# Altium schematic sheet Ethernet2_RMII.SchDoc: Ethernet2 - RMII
size A3; Project: Project name; Date: Not used; ApprovedBy: Not used; CheckedBy: Not used; Author: Not used; CompanyName: STMicroelectronics; DrawnBy: Not used; Engineer: Not used; Organization: Not used; Address1: Not used; Address2: Not used; Address3: Not used; Address4: Not used; DocumentNumber: 8; Revision: Not used; SheetNumber: 8; SheetTotal: 17
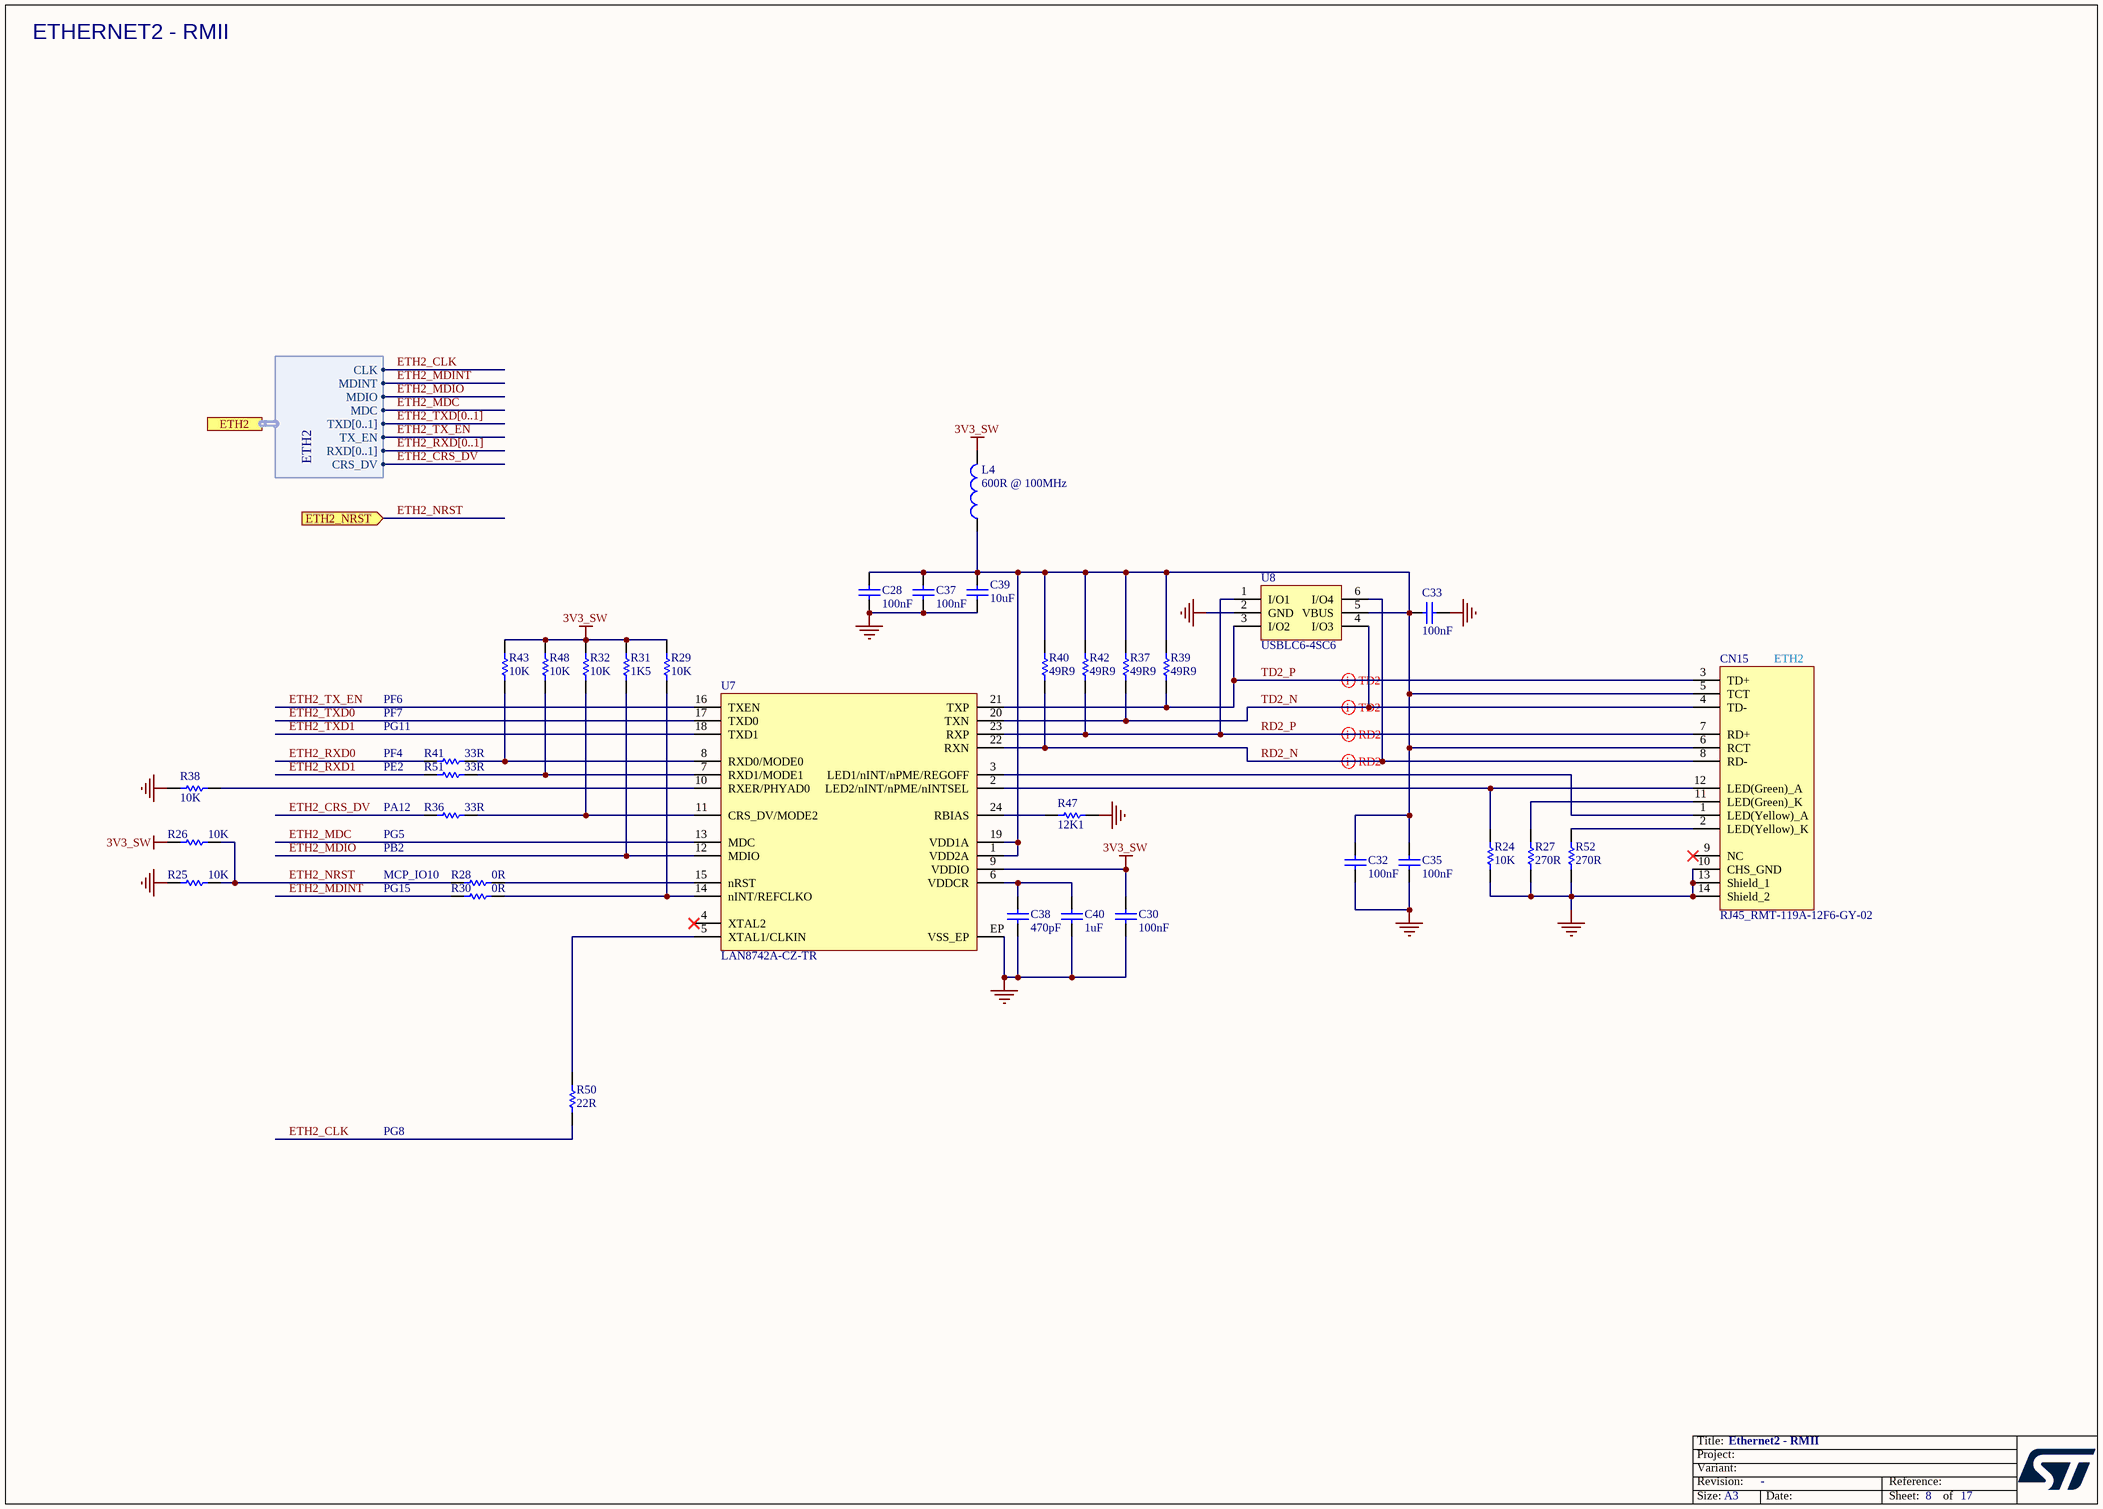
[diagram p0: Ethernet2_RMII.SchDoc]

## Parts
C28  value 100nF  [C0402]  (hidden comment: Capacitor)
C30  value 100nF  [C0402]  (hidden comment: Capacitor)
C32  value 100nF  [C0402]  (hidden comment: Capacitor)
C33  value 100nF  [C0402]  (hidden comment: Capacitor)
C35  value 100nF  [C0402]  (hidden comment: Capacitor)
C37  value 100nF  [C0402]  (hidden comment: Capacitor)
C38  value 470pF  [C0402]  (hidden comment: Capacitor)
C39  value 10uF  [C0603]  (hidden comment: Capacitor)
C40  value 1uF  [C0201_MURATA_GRM033_H0P3]  (hidden comment: Capacitor)
CN15  value RJ45_RMT-119A-12F6-GY-02  [CON_RJ45_PHC_RMT-119A-12F6-GY-02]  (hidden comment: RJ45_RTS-119A-12F6-GY-02)
L4  value 600R @ 100MHz  [L0603]  (hidden comment: BEAD)
R24  value 10K  [R0402]  (hidden comment: Resistor)
R25  value 10K  [R0402]  (hidden comment: Resistor)
R26  value 10K  [R0402]  (hidden comment: Resistor)
R27  value 270R  [R0402]  (hidden comment: Resistor)
R28  value 0R  [R0402]  (hidden comment: Resistor)
R29  value 10K  [R0402]  (hidden comment: Resistor)
R30  value 0R  [R0402]  (hidden comment: Resistor)
R31  value 1K5  [R0402]  (hidden comment: Resistor)
R32  value 10K  [R0402]  (hidden comment: Resistor)
R36  value 33R  [R0402]  (hidden comment: Resistor)
R37  value 49R9  [R0402]  (hidden comment: Resistor)
R38  value 10K  [R0402]  (hidden comment: Resistor)
R39  value 49R9  [R0402]  (hidden comment: Resistor)
R40  value 49R9  [R0402]  (hidden comment: Resistor)
R41  value 33R  [R0402]  (hidden comment: Resistor)
R42  value 49R9  [R0402]  (hidden comment: Resistor)
R43  value 10K  [R0402]  (hidden comment: Resistor)
R47  value 12K1  [R0402]  (hidden comment: Resistor)
R48  value 10K  [R0402]  (hidden comment: Resistor)
R50  value 22R  [R0402]  (hidden comment: Resistor)
R51  value 33R  [R0402]  (hidden comment: Resistor)
R52  value 270R  [R0402]  (hidden comment: Resistor)
U7  LAN8742A-CZ-TR  [ICC_VQFN24-EPAD_4X4_P050]
U8  USBLC6-4SC6  [ESD_SOT23-6L]

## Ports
ETH2 (harness ETH2), ETH2_NRST (in)

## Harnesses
ETH2: MDINT, TXD[0..1], MDIO, MDC, TX_EN, RXD[0..1], CRS_DV, CLK

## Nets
3V3_SW: C30.2 L4.2 R26.2 R29.2 R31.2 R32.2 R43.2 R48.2 U7.9(VDDIO)
GND: C28.1 C30.1 C32.1 C33.2 C35.1 C37.1 C38.1 C39.2 C40.1 CN15.10(CHS_GND) CN15.13(Shield_1) CN15.14(Shield_2) R24.1 R25.2 R27.1 R38.2 R47.2 R52.1 U7.EP(VSS_EP) U8.2(GND)
ETH2_CLK: R50.1 ; port ETH2.CLK
ETH2_CRS_DV: R36.1 ; port ETH2.CRS_DV
ETH2_MDC: U7.13(MDC) ; port ETH2.MDC
ETH2_MDINT: R30.1 ; port ETH2.MDINT
ETH2_MDIO: R31.1 U7.12(MDIO) ; port ETH2.MDIO
ETH2_NRST: R25.1 R26.1 R28.1 ; port ETH2_NRST
ETH2_RXD0: R41.1
ETH2_RXD1: R51.1
ETH2_TX_EN: U7.16(TXEN) ; port ETH2.TX_EN
ETH2_TXD0: U7.17(TXD0)
ETH2_TXD1: U7.18(TXD1)
RD2_N: CN15.8(RD-) R40.1 U7.22(RXN) U8.6(I/O4)
RD2_P: CN15.7(RD+) R42.1 U7.23(RXP) U8.1(I/O1)
TD2_N: CN15.4(TD-) R37.1 U7.20(TXN) U8.4(I/O3)
TD2_P: CN15.3(TD+) R39.1 U7.21(TXP) U8.3(I/O2)
NetC28_2: C28.2 C32.2 C33.1 C35.2 C37.2 C39.1 CN15.5(TCT) CN15.6(RCT) L4.1 R37.2 R39.2 R40.2 R42.2 U7.1(VDD2A) U7.19(VDD1A) U8.5(VBUS)
NetC38_2: C38.2 C40.2 U7.6(VDDCR)
NetCN15_1: CN15.1(LED(Yellow)_A) U7.3(LED1/nINT/nPME/REGOFF)
NetCN15_2: CN15.2(LED(Yellow)_K) R52.2
NetCN15_11: CN15.11(LED(Green)_K) R27.2
NetCN15_12: CN15.12(LED(Green)_A) R24.2 U7.2(LED2/nINT/nPME/nINTSEL)
NetR28_2: R28.2 U7.15(nRST)
NetR29_1: R29.1 R30.2 U7.14(nINT/REFCLKO)
NetR32_1: R32.1 R36.2 U7.11(CRS_DV/MODE2)
NetR38_1: R38.1 U7.10(RXER/PHYAD0)
NetR41_2: R41.2 R43.1 U7.8(RXD0/MODE0)
NetR47_1: R47.1 U7.24(RBIAS)
NetR48_1: R48.1 R51.2 U7.7(RXD1/MODE1)
NetR50_2: R50.2 U7.5(XTAL1/CLKIN)

Not connected (* = marked no-connect by the designer): CN15 9(NC)*; U7 4(XTAL2)*

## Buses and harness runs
bus ETH2_RXD[0..1]
bus ETH2_TXD[0..1]

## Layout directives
differential pair: RD2_N, RD2_P, TD2_N, TD2_P

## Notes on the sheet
- ETHERNET2 - RMII
- PF6
- PF7
- ETH2
- PF4
- PE2
- PG11
- PA12
- (near R36) PG5
- PB2
- PG15
- MCP_IO10
- PG8

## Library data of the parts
C28 C30 C32 C33 C35 C37 = MCD-00006: Capacitor, MLCC, 100nF, 16V, X7R, +/-10%, 0402, T=0.5mm; Manufacturer_Part_Number: CC0402KRX7R7BB104; Manufacturer: YAGEO; Part_Preference: Recommended; Partial_Alternate_Internal_Part_Number: MCD-03299; Order_Code_RS: 9402047; Component_Country_Of_Origin: China; ShowFields: YES; ID: 2474
C38 = MCD-00724: Capacitor, MLCC, 470pF, 50V, NPO, +/-5%, 0402, T=0.5mm; Manufacturer_Part_Number: CC0402JRNPO9BN471; Manufacturer: YAGEO; Part_Preference: Recommended; Order_Code_RS: 199-2186; Component_Country_Of_Origin: China; ShowFields: YES; ID: 3023
C39 = MCD-00099: Capacitor, MLCC, 10uF, 10V, X5R, +/-10%, 0603, T=0.8mm; Manufacturer_Part_Number: GRM188R61A106KE69; Manufacturer: MURATA; Part_Preference: Recommended; Partial_Alternate_Internal_Part_Number: MCD-03152; Order_Code_RS: 2494233; Component_Country_Of_Origin: Japan°°; ShowFields: YES; ID: 2770
C40 = MCD-02377: Capacitor, MLCC, 1uF, 6.3V, X5R, +/-20%, 0201, T=0,3mm; Manufacturer_Part_Number: GRM033R60J105MEA2; Manufacturer: MURATA; Part_Preference: Recommended; Partial_Alternate_Internal_Part_Number: MCD-04356; Order_Code_RS: 820-0643; Component_Country_Of_Origin: Japan°; ShowFields: YES; ID: 4483
CN15 = MCD-02475: connector_RJ45, 10/100 Ethernet integrated MAG with integrate Green and Yellow LED, T= 13.61mm; Part_Preference: Recommended; Manufacturer: PENGHUI; Manufacturer_Part_Number: RMT-119A-12F6-GY-02; ShowFields: YES; ID: 4581; Component_Country_Of_Origin: China
L4 = MCD-00047: Ferrite bead, 600R @1 00MHz, +/-25%, 350mA, 0R5, 0603, T=0.8mm; Part_Type: Inductor; Manufacturer_Part_Number: FCM1608KF-601T03; Manufacturer: TAI-TECH; Part_Preference: Recommended; Partial_Alternate_Internal_Part_Number: MCD-02959; Component_Country_Of_Origin: Unknown; ShowFields: YES; ID: 2546
R24 R29 R32 R38 R43 R48 = MCD-00053: Resistor, 10K, 0402, +/-1%, 1/16W; Manufacturer_Part_Number: RC0402FR-0710KL; Manufacturer: YAGEO; BMS_Part_Number: 9131590; Part_Preference: Recommended; Order_Code_RS: 9239359; Component_Country_Of_Origin: China; ShowFields: YES; ID: 2539
R25 R26 = MCD-00053: Resistor, 10K, 0402, +/-1%, 1/16W; Manufacturer_Part_Number: RC0402FR-0710KL; Manufacturer: YAGEO; Part_Preference: Recommended; BMS_Part_Number: 9131590; Order_Code_RS: 9239359; Component_Country_Of_Origin: China; ShowFields: YES; ID: 2539
R27 R52 = MCD-00441: Resistor, 270R, 0402, +/-1%, 1/16W; Manufacturer_Part_Number: RC0402FR-07270RL; Manufacturer: YAGEO; Part_Preference: Recommended; Component_Country_Of_Origin: China; ShowFields: YES; ID: 2838
R28 = MCD-00052: Resistor, 0R, 0402, +/-5%, 1/16W; Part_Preference: Recommended; Manufacturer: YAGEO; Manufacturer_Part_Number: RC0402JR-070RL; Order_Code_RS: 9232516RL; Component_Country_Of_Origin: China; ShowFields: YES; ID: 2540
R30 = MCD-00052: Resistor, 0R, 0402, +/-5%, 1/16W; Manufacturer_Part_Number: RC0402JR-070RL; Manufacturer: YAGEO; Part_Preference: Recommended; Order_Code_RS: 9232516RL; Component_Country_Of_Origin: China; ShowFields: YES; ID: 2540
R31 = MCD-00068: Resistor, 1K5, 0402, +/-1%, 1/16W; Manufacturer_Part_Number: RC0402FR-071K5L; Manufacturer: YAGEO; Part_Preference: Recommended; Order_Code_RS: 9239251; Component_Country_Of_Origin: China; ShowFields: YES; ID: 2524
R36 R41 R51 = MCD-00455: Resistor, 33R, 0402, +/-1%, 1/16W; Manufacturer_Part_Number: RC0402FR-0733RL; Manufacturer: YAGEO; Part_Preference: Recommended; Component_Country_Of_Origin: China; ShowFields: YES; ID: 2821
R37 R39 R40 R42 = MCD-00565: Resistor, 49R9, 0402, +/-1%, 1/16W; Manufacturer_Part_Number: RC0402FR-0749R9L; Manufacturer: YAGEO; Part_Preference: Recommended; Component_Country_Of_Origin: China; ShowFields: YES; ID: 3178
R47 = MCD-00723: Resistor, 12K1, 0402, +/-1%, 1/16W; Manufacturer_Part_Number: RC0402FR-0712K1L; Manufacturer: YAGEO; Part_Preference: Recommended; Component_Country_Of_Origin: China; ShowFields: YES; ID: 3022
R50 = MCD-00189: Resistor, 22R, 0402, +/-1%, 1/16W; Manufacturer_Part_Number: RC0402FR-0722RL; Manufacturer: YAGEO; Part_Preference: Recommended; Component_Country_Of_Origin: China; ShowFields: YES; ID: 2677
U7 = MCD-00719: 10/100M RMII Ethernet transceiver; Part_Type: IC; Manufacturer: MICROCHIP; BMS_Part_Number: 9177984; Part_Preference: Recommended; Partial_Alternate_Internal_Part_Number: MCD-03200; Component_Country_Of_Origin: Unknown; ShowFields: YES; ID: 3026; Order_Code_RS: 215-3925
U8 = MCD-00250: Very low capacitance ESD protection , 4 lines; Part_Type: Diode; Manufacturer: STMICROELECTRONICS; BMS_Part_Number: 9151001; Part_Preference: Recommended; Manufacturer_HQ_COO: EU; Component_Country_Of_Origin: China; ShowFields: YES; ID: 2616; Order_Code_RS: 920-6272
